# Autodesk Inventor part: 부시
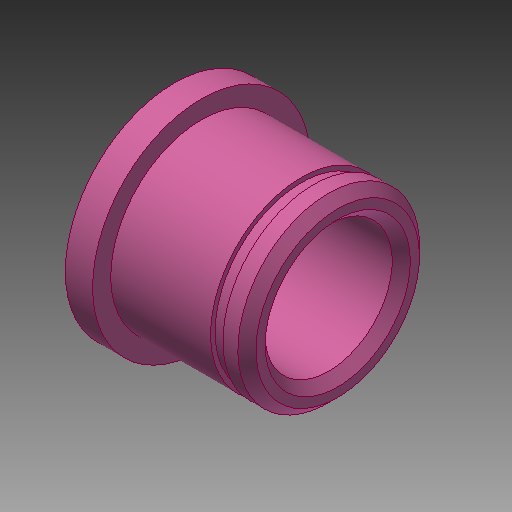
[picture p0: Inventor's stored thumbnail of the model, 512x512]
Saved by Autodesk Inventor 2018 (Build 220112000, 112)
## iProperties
Created: 2019-01
Part Number: 부시
Material: 강철, 연강
Document SubType Name: Modeling
Designer: mduedu
Density: 7.86 g/cm^3
Appearance: 분홍색
Mass: 25.1828 g
Surface Area: 25.5171 cm^2
Volume: 3.20391 cm^3
Author: mduedu
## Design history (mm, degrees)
sketch "스케치1"
  geometry: L1 (0, 0)-(3, 0); L2 (3, 0)-(3, 12); L3 (3, 12)-(0, 12); L4 (0, 12)-(0, 0); L5 (3, 0)-(18, 0); L6 (18, 0)-(18, 10); L7 (18, 10)-(3, 10); L8 (3, 10)-(3, 0)
  constraints: 16 end point, 4 parallel, 2 horizontal, 2 perpendicular
  dimensions: "d0" = 18 distance between parallel lines of L6 L4; "d2" = 3 distance of L2.end L3.end; "d3" = 24 diameter of L3 L1; "d4" = 20 diameter of L7 L5
revolve "회전1" sketch "스케치1" stored, may be unused: angle "d5" = 90 deg
sketch "스케치2"
  geometry: C1 r 7 at (0, 0); 1 further point
  constraints: 1 centre point, 1 coincident
  dimensions: "d6" = 14 diameter of C1
extrude "돌출1" cut sketch "스케치2" extent not by distance; stored distance "d7" = 10; taper "d8" = 0 deg
chamfer "모따기1" distance "d9" = 1; stored, may be unused: second distance "d10" = 2, angle "d11" = 45 deg
node "작업 평면1"
sketch "스케치3"
  geometry: C1 r 9.5 at (0, 0); C2 r 10 at (0, 0) reference; 1 further point
  constraints: 1 centre point, 1 coincident
  dimensions: "d13" = 19 diameter of C1
extrude "돌출2" cut sketch "스케치3" distance "d14" = 1.35; taper "d15" = 0 deg
node "솔리드1"
other parameters: "d12" = 11
